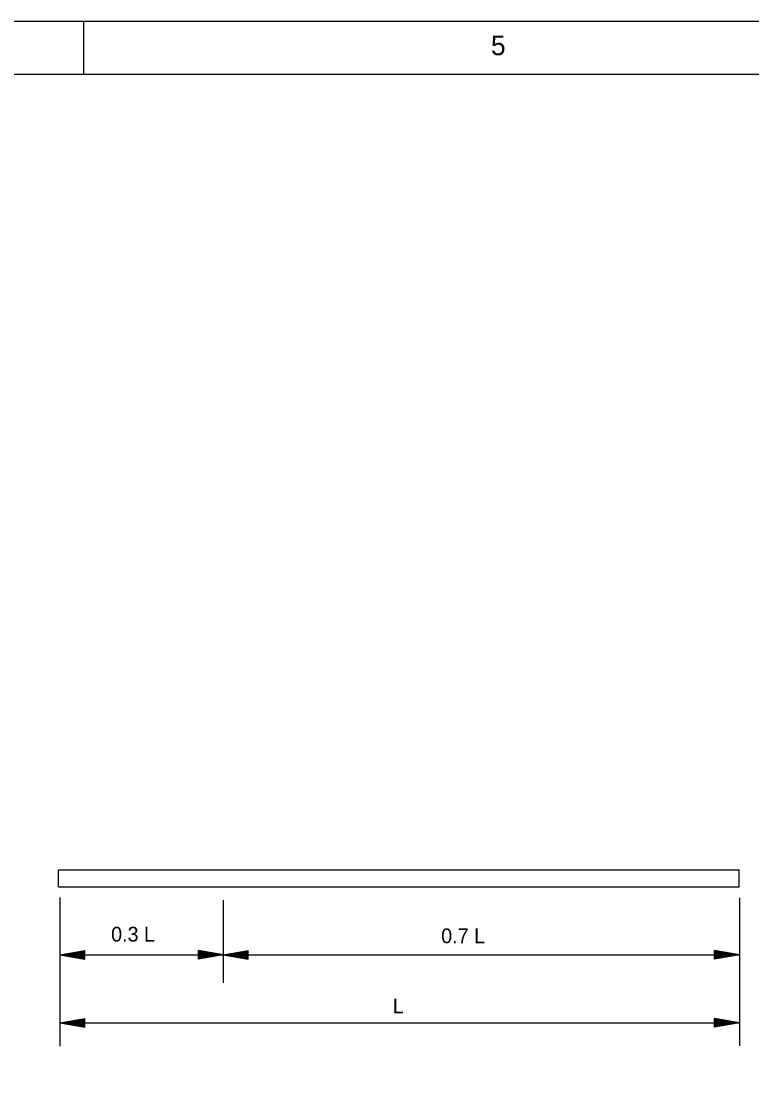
# Model space of a CAD drawing. Extents: x 44742.26 to 44749.63, y 44739 to 44741.19.
# Drawn here: x 44744.335 to 44744.782, y 44740.541 to 44741.188 of the extents above; entities that cross this region are included whole.
import ezdxf

# ---------------------------------------------------------------- set-up
doc = ezdxf.new("R2010")
doc.units = 0
for name, color, linetype in [('Level 1', 7, 'Continuous'), ('Level 10', 7, 'Continuous'), ('Level 7', 7, 'Continuous'), ('Level 9', 7, 'Continuous')]:
    doc.layers.add(name, color=color, linetype=linetype)

msp = doc.modelspace()

# ---------------------------------------------------------------- linework, layer by layer
at = {"layer": 'Level 1'}
for p, q in [((44744.35853, 44740.6521), (44744.35853, 44740.56117)), ((44744.45849, 44740.65053), (44744.45849, 44740.59993)), ((44744.77437, 44740.65184), (44744.77437, 44740.5613)), ((44744.35853, 44740.61704), (44744.37376, 44740.61963)), ((44744.35853, 44740.61704), (44744.77437, 44740.61704)), ((44744.35853, 44740.61704), (44744.37376, 44740.61704)), ((44744.35853, 44740.61704), (44744.37376, 44740.61445)), ((44744.36132, 44740.61725), (44744.37309, 44740.61925)), ((44744.37344, 44740.6174), (44744.36132, 44740.61725)), ((44744.37344, 44740.61667), (44744.36132, 44740.61681)), ((44744.36132, 44740.61681), (44744.37309, 44740.61482)), ((44744.36466, 44740.61756), (44744.37274, 44740.6189)), ((44744.37308, 44740.61771), (44744.36466, 44740.61756)), ((44744.36466, 44740.6165), (44744.37274, 44740.61517)), ((44744.37308, 44740.61636), (44744.36466, 44740.6165)), ((44744.36791, 44740.61784), (44744.37242, 44740.61852)), ((44744.37273, 44740.61799), (44744.36791, 44740.61784)), ((44744.36791, 44740.61623), (44744.37242, 44740.61554)), ((44744.37273, 44740.61609), (44744.36791, 44740.61623)), ((44744.37242, 44740.61817), (44744.37102, 44740.61811)), ((44744.37242, 44740.6159), (44744.37102, 44740.61596)), ((44744.37242, 44740.61852), (44744.37242, 44740.61817)), ((44744.37242, 44740.61554), (44744.37242, 44740.6159)), ((44744.37274, 44740.6189), (44744.37273, 44740.61799)), ((44744.37274, 44740.61517), (44744.37273, 44740.61609)), ((44744.37309, 44740.61925), (44744.37308, 44740.61771)), ((44744.37309, 44740.61482), (44744.37308, 44740.61636)), ((44744.37342, 44740.61925), (44744.37344, 44740.6174)), ((44744.37342, 44740.61482), (44744.37344, 44740.61667)), ((44744.37376, 44740.61445), (44744.37376, 44740.61963)), ((44744.44325, 44740.61445), (44744.44325, 44740.61963)), ((44744.45849, 44740.61704), (44744.44325, 44740.61963)), ((44744.45849, 44740.61704), (44744.44325, 44740.61704)), ((44744.45849, 44740.61704), (44744.44325, 44740.61445)), ((44744.44357, 44740.61925), (44744.44357, 44740.6174)), ((44744.44357, 44740.6174), (44744.45569, 44740.61725)), ((44744.44357, 44740.61667), (44744.45569, 44740.61681)), ((44744.44357, 44740.61482), (44744.44357, 44740.61667)), ((44744.45569, 44740.61725), (44744.44391, 44740.61925)), ((44744.44391, 44740.61925), (44744.44393, 44740.61771)), ((44744.45569, 44740.61681), (44744.44391, 44740.61482)), ((44744.44391, 44740.61482), (44744.44393, 44740.61636)), ((44744.44393, 44740.61771), (44744.45234, 44740.61756)), ((44744.44393, 44740.61636), (44744.45234, 44740.6165)), ((44744.45234, 44740.61756), (44744.44428, 44740.6189)), ((44744.44428, 44740.6189), (44744.44428, 44740.61799)), ((44744.44428, 44740.61799), (44744.4491, 44740.61784)), ((44744.45234, 44740.6165), (44744.44428, 44740.61517)), ((44744.44428, 44740.61609), (44744.4491, 44740.61623)), ((44744.44428, 44740.61517), (44744.44428, 44740.61609)), ((44744.44459, 44740.61852), (44744.44458, 44740.61817)), ((44744.44458, 44740.61817), (44744.44598, 44740.61811)), ((44744.44458, 44740.6159), (44744.44598, 44740.61596)), ((44744.44459, 44740.61554), (44744.44458, 44740.6159)), ((44744.4491, 44740.61784), (44744.44459, 44740.61852)), ((44744.4491, 44740.61623), (44744.44459, 44740.61554)), ((44744.45849, 44740.61704), (44744.47372, 44740.61963)), ((44744.45849, 44740.61704), (44744.47372, 44740.61704)), ((44744.45849, 44740.61704), (44744.47372, 44740.61445)), ((44744.46128, 44740.61725), (44744.47305, 44740.61925)), ((44744.4734, 44740.6174), (44744.46128, 44740.61725)), ((44744.4734, 44740.61667), (44744.46128, 44740.61681)), ((44744.46128, 44740.61681), (44744.47305, 44740.61482)), ((44744.46462, 44740.61756), (44744.47269, 44740.6189)), ((44744.47304, 44740.61771), (44744.46462, 44740.61756)), ((44744.46462, 44740.6165), (44744.47269, 44740.61517)), ((44744.47304, 44740.61636), (44744.46462, 44740.6165)), ((44744.46787, 44740.61784), (44744.47238, 44740.61852)), ((44744.47268, 44740.61799), (44744.46787, 44740.61784)), ((44744.46787, 44740.61623), (44744.47238, 44740.61554)), ((44744.47268, 44740.61609), (44744.46787, 44740.61623)), ((44744.47238, 44740.61817), (44744.47099, 44740.61811)), ((44744.47238, 44740.6159), (44744.47099, 44740.61596)), ((44744.47238, 44740.61852), (44744.47238, 44740.61817)), ((44744.47238, 44740.61554), (44744.47238, 44740.6159)), ((44744.47269, 44740.6189), (44744.47268, 44740.61799)), ((44744.47269, 44740.61517), (44744.47268, 44740.61609)), ((44744.47305, 44740.61925), (44744.47304, 44740.61771)), ((44744.47305, 44740.61482), (44744.47304, 44740.61636)), ((44744.47338, 44740.61925), (44744.4734, 44740.6174)), ((44744.47338, 44740.61482), (44744.4734, 44740.61667)), ((44744.47372, 44740.61445), (44744.47372, 44740.61963)), ((44744.75913, 44740.61445), (44744.75913, 44740.61963)), ((44744.77437, 44740.61704), (44744.75913, 44740.61963)), ((44744.77437, 44740.61704), (44744.75913, 44740.61704)), ((44744.77437, 44740.61704), (44744.75913, 44740.61445)), ((44744.75947, 44740.61925), (44744.75944, 44740.6174)), ((44744.75944, 44740.6174), (44744.77158, 44740.61725)), ((44744.75944, 44740.61667), (44744.77158, 44740.61681)), ((44744.75947, 44740.61482), (44744.75944, 44740.61667)), ((44744.77158, 44740.61725), (44744.7598, 44740.61925)), ((44744.7598, 44740.61925), (44744.75981, 44740.61771)), ((44744.77158, 44740.61681), (44744.7598, 44740.61482)), ((44744.7598, 44740.61482), (44744.75981, 44740.61636)), ((44744.75981, 44740.61771), (44744.76822, 44740.61756)), ((44744.75981, 44740.61636), (44744.76822, 44740.6165)), ((44744.76822, 44740.61756), (44744.76015, 44740.6189)), ((44744.76015, 44740.6189), (44744.76016, 44740.61799)), ((44744.76822, 44740.6165), (44744.76015, 44740.61517)), ((44744.76015, 44740.61517), (44744.76016, 44740.61609)), ((44744.76016, 44740.61799), (44744.76498, 44740.61784)), ((44744.76016, 44740.61609), (44744.76498, 44740.61623)), ((44744.76048, 44740.61852), (44744.76047, 44740.61817)), ((44744.76047, 44740.61817), (44744.76186, 44740.61811)), ((44744.76047, 44740.6159), (44744.76186, 44740.61596)), ((44744.76048, 44740.61554), (44744.76047, 44740.6159)), ((44744.76498, 44740.61784), (44744.76048, 44740.61852)), ((44744.76498, 44740.61623), (44744.76048, 44740.61554)), ((44744.35853, 44740.57539), (44744.37376, 44740.57797)), ((44744.35853, 44740.57539), (44744.77437, 44740.57539)), ((44744.35853, 44740.57539), (44744.37376, 44740.57539)), ((44744.35853, 44740.57539), (44744.37376, 44740.5728)), ((44744.36132, 44740.57561), (44744.37309, 44740.5776)), ((44744.37344, 44740.57575), (44744.36132, 44740.57561)), ((44744.37344, 44740.57502), (44744.36132, 44740.57517)), ((44744.36132, 44740.57517), (44744.37309, 44740.57318)), ((44744.36466, 44740.57592), (44744.37274, 44740.57725)), ((44744.37308, 44740.57606), (44744.36466, 44740.57592)), ((44744.36466, 44740.57486), (44744.37274, 44740.57352)), ((44744.37308, 44740.57471), (44744.36466, 44740.57486)), ((44744.36791, 44740.57619), (44744.37242, 44740.57688)), ((44744.37273, 44740.57634), (44744.36791, 44740.57619)), ((44744.37242, 44740.57652), (44744.37102, 44740.57646)), ((44744.37242, 44740.57688), (44744.37242, 44740.57652)), ((44744.37274, 44740.57725), (44744.37273, 44740.57634)), ((44744.37309, 44740.5776), (44744.37308, 44740.57606)), ((44744.37309, 44740.57318), (44744.37308, 44740.57471)), ((44744.37342, 44740.5776), (44744.37344, 44740.57575)), ((44744.37342, 44740.57318), (44744.37344, 44740.57502)), ((44744.37376, 44740.5728), (44744.37376, 44740.57797)), ((44744.75913, 44740.5728), (44744.75913, 44740.57797)), ((44744.77437, 44740.57539), (44744.75913, 44740.57797)), ((44744.77437, 44740.57539), (44744.75913, 44740.57539)), ((44744.77437, 44740.57539), (44744.75913, 44740.5728)), ((44744.75947, 44740.5776), (44744.75944, 44740.57575)), ((44744.75944, 44740.57575), (44744.77158, 44740.57561)), ((44744.75944, 44740.57502), (44744.77158, 44740.57517)), ((44744.75947, 44740.57318), (44744.75944, 44740.57502)), ((44744.77158, 44740.57561), (44744.7598, 44740.5776)), ((44744.7598, 44740.5776), (44744.75981, 44740.57606)), ((44744.77158, 44740.57517), (44744.7598, 44740.57318)), ((44744.7598, 44740.57318), (44744.75981, 44740.57471)), ((44744.75981, 44740.57606), (44744.76822, 44740.57592)), ((44744.75981, 44740.57471), (44744.76822, 44740.57486)), ((44744.76822, 44740.57592), (44744.76015, 44740.57725)), ((44744.76015, 44740.57725), (44744.76016, 44740.57634)), ((44744.76822, 44740.57486), (44744.76015, 44740.57352)), ((44744.76016, 44740.57634), (44744.76498, 44740.57619)), ((44744.76048, 44740.57688), (44744.76047, 44740.57652)), ((44744.76047, 44740.57652), (44744.76186, 44740.57646)), ((44744.76498, 44740.57619), (44744.76048, 44740.57688)), ((44744.36791, 44740.57459), (44744.37242, 44740.5739)), ((44744.37273, 44740.57443), (44744.36791, 44740.57459)), ((44744.37242, 44740.57425), (44744.37102, 44740.57431)), ((44744.37242, 44740.5739), (44744.37242, 44740.57425)), ((44744.37274, 44740.57352), (44744.37273, 44740.57443)), ((44744.76015, 44740.57352), (44744.76016, 44740.57443)), ((44744.76016, 44740.57443), (44744.76498, 44740.57459)), ((44744.76047, 44740.57425), (44744.76186, 44740.57431)), ((44744.76048, 44740.5739), (44744.76047, 44740.57425)), ((44744.76498, 44740.57459), (44744.76048, 44740.5739))]:
    msp.add_line(p, q, dxfattribs=at)
msp.add_lwpolyline([(44742.25988, 44741.18835), (44745.08727, 44741.18835), (44745.08727, 44739.00305), (44742.25988, 44739.00305)], close=True, dxfattribs=at)
at = {"layer": 'Level 10'}
msp.add_line((44744.37323, 44741.15596), (44744.37323, 44741.18835), dxfattribs=at)
at = {"layer": 'Level 7'}
for p, q in [((44744.35769, 44740.66911), (44744.77419, 44740.66911)), ((44744.35769, 44740.65869), (44744.35769, 44740.66911)), ((44744.77419, 44740.65869), (44744.77419, 44740.66911)), ((44744.35769, 44740.65869), (44744.77419, 44740.65869))]:
    msp.add_line(p, q, dxfattribs=at)
at = {"layer": 'Level 9'}
msp.add_line((44742.35627, 44741.15596), (44744.8783, 44741.15596), dxfattribs=at)

# ---------------------------------------------------------------- texts
at = {"layer": 'Level 1'}
msp.add_text('5', height=0.01203, dxfattribs=at).set_placement((44744.6223, 44741.16753))
at = {"layer": 'Level 7'}
for s, p in [('0.3 L', (44744.38986, 44740.62513)), ('0.7 L', (44744.59182, 44740.62412)), ('L', (44744.56222, 44740.58113))]:
    msp.add_text(s, height=0.00902, dxfattribs=at).set_placement(p)

doc.saveas('drawing.dxf')
